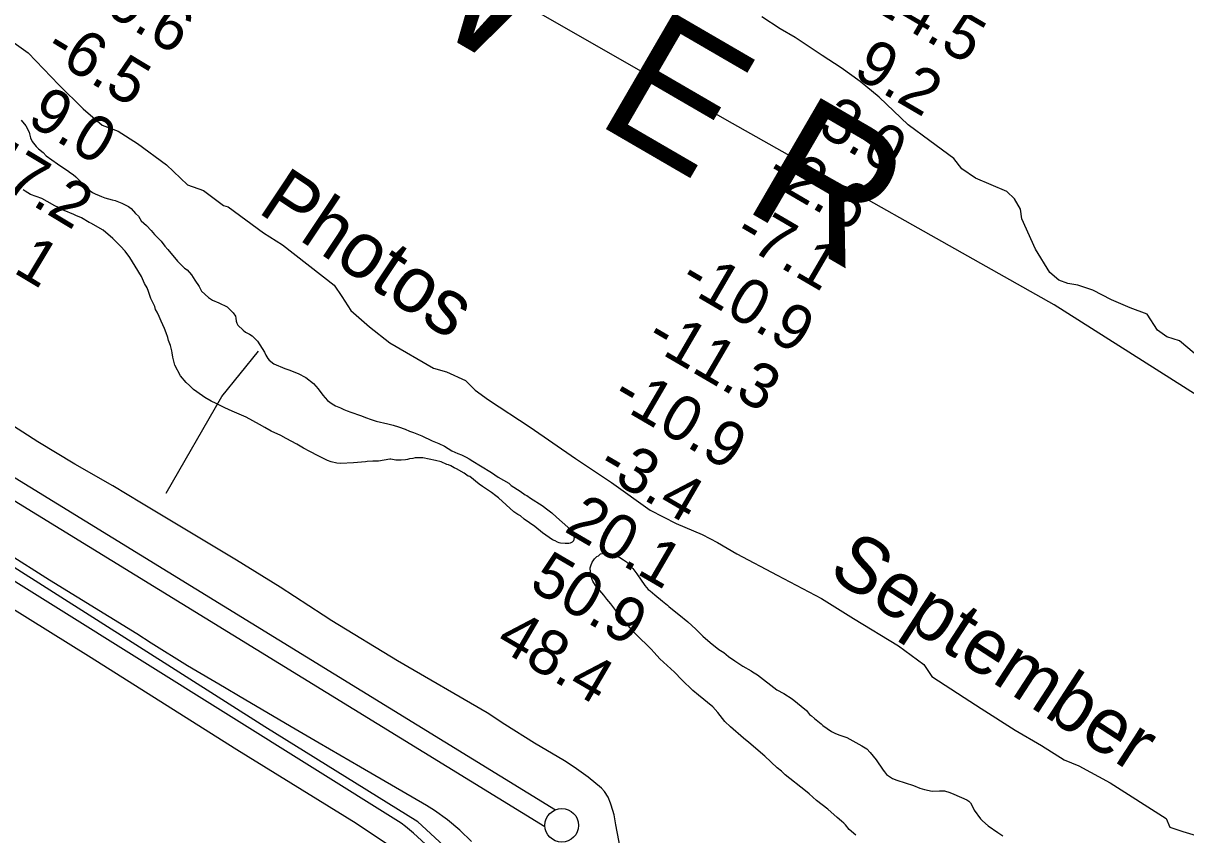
# Model space of a CAD drawing. Extents: x 3146026 to 3183936, y 897894 to 923344.
# Drawn here: x 3156715 to 3158441, y 912037 to 913242 of the extents above; entities that cross this region are included whole.
import ezdxf

# ---------------------------------------------------------------- set-up
doc = ezdxf.new("R2010")
doc.units = 0
for name, color, linetype in [('V-LEVE-TOET', 7, 'Continuous'), ('V-RIVR-EDGE', 7, 'Continuous'), ('V-RIVR-IDEN', 7, 'Continuous'), ('V-RIVR-RANG', 7, 'Continuous'), ('V-ROAD-CNTR', 7, 'Continuous'), ('V-SITE-VEGE', 7, 'Continuous'), ('V-SURV-LINE', 7, 'Continuous'), ('V-TOPO-BNDY', 7, 'Continuous'), ('V-TOPO-SHOR', 7, 'Continuous')]:
    doc.layers.add(name, color=color, linetype=linetype)

msp = doc.modelspace()

# ---------------------------------------------------------------- linework, layer by layer
at = {"layer": 'V-LEVE-TOET'}
for points in [[(3157594.4, 912051.6), (3157591.9, 912066.4), (3157587.8, 912081), (3157586.9, 912083.7), (3157583.1, 912092.6), (3157577.9, 912100.8), (3157573.2, 912106.2), (3157553.3, 912122.4), (3157532.5, 912137.4), (3157518.5, 912146.4), (3157473.7, 912172.7), (3157429.6, 912200.3), (3157403.4, 912217.7), (3157270.6, 912294.8), (3157173.1, 912354.6), (3157160.2, 912362.6), (3157096.1, 912404.3), (3157031.2, 912444.6), (3156890.3, 912529), (3156847.6, 912554.9), (3156791.6, 912586.8), (3156736.4, 912620.2), (3156684.8, 912653.1)], [(3157380.4, 912027), (3157363.1, 912043.5), (3157344.7, 912058.8), (3157325.3, 912072.9), (3157313.7, 912080.4), (3157215.3, 912137.4), (3157153.9, 912172.7), (3157118.5, 912193.8), (3157036.9, 912241.5), (3157013.4, 912255.5), (3156958.6, 912287.8), (3156904.5, 912321.4), (3156883.5, 912334.9), (3156753.6, 912414.9), (3156625.5, 912495.9)], [(3157603.4, 912005.1), (3157594.4, 912051.6)]]:
    msp.add_lwpolyline(points, dxfattribs=at)
at = {"layer": 'V-RIVR-EDGE'}
for points in [[(3158453.2, 912751.6), (3158431.6, 912770.3), (3158412.4, 912776.1), (3158399, 912786.2), (3158383.6, 912809.7), (3158358, 912818.9), (3158330.3, 912831.1), (3158302.9, 912845.5), (3158280.7, 912852.9), (3158265.5, 912855.3), (3158252.4, 912860.2), (3158239.1, 912871.8), (3158217.8, 912906), (3158197.2, 912951.4), (3158195.4, 912965.4), (3158186.6, 912981), (3158175.1, 912991.7), (3158128.8, 913011.6), (3158108.5, 913025.7), (3158096.6, 913040.6), (3158060.8, 913067.2), (3158028.5, 913090.7), (3157985.4, 913132), (3157957.1, 913154.9), (3157929.2, 913175.3), (3157900.9, 913193.7), (3157860.7, 913220.6), (3157838.8, 913233.4), (3157811.5, 913250.9)], [(3156669.9, 913235), (3156722.2, 913197.6), (3156767.7, 913150.3), (3156803.7, 913114.5), (3156831.8, 913090.3), (3156855.5, 913081.5), (3156884.4, 913063.2), (3156927.6, 913031.3), (3156958.9, 913001.9), (3156982.2, 912993.5), (3157012.3, 912970.8), (3157019.1, 912969.2), (3157071.3, 912930.6), (3157099.8, 912912.7), (3157176.6, 912852.7), (3157187.7, 912836), (3157201.1, 912815.3), (3157228.8, 912791.1), (3157259.3, 912767.2), (3157323.8, 912729.3), (3157343.3, 912724.1), (3157371.4, 912711.4), (3157385.6, 912697.1), (3157405.4, 912682.7), (3157467.6, 912642.1), (3157534.5, 912595.2), (3157588.3, 912559.7), (3157645.4, 912518.8), (3157684.2, 912498.8), (3157722.6, 912482.5), (3157745.6, 912470.9), (3157774.1, 912453.8), (3157834.3, 912422.3), (3157900, 912387.6), (3157947.2, 912357.8), (3158014.1, 912317.2), (3158051.7, 912289.7), (3158063.9, 912271.8), (3158111.5, 912240.8), (3158137.2, 912224.1), (3158187.5, 912192.2), (3158226.7, 912169.5), (3158260.3, 912148), (3158282.1, 912139.2), (3158328.5, 912114.1), (3158411.6, 912061.2), (3158417.2, 912048.1), (3158436.6, 912041.7), (3158456.4, 912035.7)]]:
    msp.add_lwpolyline(points, dxfattribs=at)
at = {"layer": 'V-ROAD-CNTR'}
msp.add_lwpolyline([(3157275.9, 912053.9), (3155853.5, 912943.3)], dxfattribs=at)
msp.add_arc((3157003.3, 911700), 446.8, 36.1726, 52.3968, dxfattribs=at)
at = {"layer": 'V-SITE-VEGE'}
for p, q in [((3156711.7, 913097.7), (3156718.9, 913089.3)), ((3156718.9, 913089.3), (3156723.6, 913079.7)), ((3156723.6, 913079.7), (3156724, 913077.2)), ((3156724, 913077.2), (3156725.7, 913071.3)), ((3156725.7, 913071.3), (3156728.3, 913065.9)), ((3156728.3, 913065.9), (3156733.8, 913058.8)), ((3156733.8, 913058.8), (3156737.6, 913055)), ((3156737.6, 913055), (3156744.3, 913049.6)), ((3156744.3, 913049.6), (3156748.9, 913044.6)), ((3156748.9, 913044.6), (3156765.8, 913032.9)), ((3156765.8, 913032.9), (3156773.4, 913027.5)), ((3156773.4, 913027.5), (3156780.5, 913023)), ((3156780.5, 913023), (3156785.2, 913019.6)), ((3156785.2, 913019.6), (3156789, 913017.1)), ((3156789, 913017.1), (3156792.8, 913013.8)), ((3156792.8, 913013.8), (3156804.1, 913002.1)), ((3156717.8, 912992.4), (3156714.8, 912994.1)), ((3156725.8, 912987.4), (3156717.8, 912992.4)), ((3156742.2, 912981.2), (3156725.8, 912987.4)), ((3156804.1, 913002.1), (3156812.2, 912994.2)), ((3156812.2, 912994.2), (3156814.3, 912992.9)), ((3156814.3, 912992.9), (3156817.6, 912990.4)), ((3156817.6, 912990.4), (3156821.4, 912988.4)), ((3156821.4, 912988.4), (3156827.3, 912985.9)), ((3156750.2, 912977), (3156742.2, 912981.2)), ((3156761.9, 912970.4), (3156750.2, 912977)), ((3156767, 912968.3), (3156761.9, 912970.4)), ((3156827.3, 912985.9), (3156831.1, 912984.6)), ((3156831.1, 912984.6), (3156836.1, 912982.6)), ((3156836.1, 912982.6), (3156846.7, 912979.3)), ((3156846.7, 912979.3), (3156851.3, 912978.5)), ((3156851.3, 912978.5), (3156861.4, 912974.7)), ((3156861.4, 912974.7), (3156871, 912969.7)), ((3156871, 912969.7), (3156874.8, 912966.8)), ((3156775.8, 912963.8), (3156767, 912968.3)), ((3156790.1, 912957.6), (3156775.8, 912963.8)), ((3156792.7, 912956.3), (3156790.1, 912957.6)), ((3156801.5, 912952.6), (3156792.7, 912956.3)), ((3156812.9, 912945.9), (3156801.5, 912952.6)), ((3156874.8, 912966.8), (3156881.6, 912959.3)), ((3156881.6, 912959.3), (3156885.8, 912955.1)), ((3156885.8, 912955.1), (3156890, 912948.5)), ((3156815.4, 912944.7), (3156812.9, 912945.9)), ((3156833.5, 912934.3), (3156815.4, 912944.7)), ((3156890, 912948.5), (3156897.6, 912941.4)), ((3156897.6, 912941.4), (3156904.8, 912933.9)), ((3156847.8, 912922.2), (3156833.5, 912934.3)), ((3156859.2, 912910.9), (3156847.8, 912922.2)), ((3156904.8, 912933.9), (3156909.5, 912928)), ((3156909.5, 912928), (3156919.6, 912918)), ((3156919.6, 912918), (3156925.1, 912910.5)), ((3156866, 912903), (3156859.2, 912910.9)), ((3156873.1, 912893.8), (3156866, 912903)), ((3156925.1, 912910.5), (3156929.7, 912905.5)), ((3156929.7, 912905.5), (3156943.7, 912888.3)), ((3156881.2, 912880.9), (3156873.1, 912893.8)), ((3156943.7, 912888.3), (3156954.2, 912877.9)), ((3156890.5, 912865.4), (3156881.2, 912880.9)), ((3156954.2, 912877.9), (3156958, 912875.4)), ((3156958, 912875.4), (3156964.8, 912868.3)), ((3156964.8, 912868.3), (3156969.4, 912860.4)), ((3156894.8, 912855.3), (3156890.5, 912865.4)), ((3156898.6, 912848.6), (3156894.8, 912855.3)), ((3156900.7, 912843.2), (3156898.6, 912848.6)), ((3156969.4, 912860.4), (3156975.8, 912850.8)), ((3156975.8, 912850.8), (3156979.6, 912844.1)), ((3156904.1, 912833.2), (3156900.7, 912843.2)), ((3156907.9, 912826), (3156904.1, 912833.2)), ((3156979.6, 912844.1), (3156989.7, 912834.5)), ((3156989.7, 912834.5), (3156996, 912830.7)), ((3156910, 912821), (3156907.9, 912826)), ((3156911.3, 912816.4), (3156910, 912821)), ((3156913.5, 912812.6), (3156911.3, 912816.4)), ((3156996, 912830.7), (3157005.3, 912826.6)), ((3157005.3, 912826.6), (3157017.5, 912820.4)), ((3157017.5, 912820.4), (3157019.1, 912819.1)), ((3157019.1, 912819.1), (3157026.7, 912811.6)), ((3156916.4, 912806.4), (3156913.5, 912812.6)), ((3156919.4, 912799.3), (3156916.4, 912806.4)), ((3156924.5, 912788.4), (3156919.4, 912799.3)), ((3157026.7, 912811.6), (3157029.7, 912806.6)), ((3157029.7, 912806.6), (3157030.6, 912803.6)), ((3157030.6, 912803.6), (3157031, 912799.5)), ((3157031, 912799.5), (3157031.9, 912796.5)), ((3157031.9, 912796.5), (3157033.6, 912793.2)), ((3156927, 912782.1), (3156924.5, 912788.4)), ((3156929.6, 912775), (3156927, 912782.1)), ((3157033.6, 912793.2), (3157041.2, 912786.1)), ((3157041.2, 912786.1), (3157044.9, 912783.2)), ((3157044.9, 912783.2), (3157050.8, 912779.8)), ((3157050.8, 912779.8), (3157054.6, 912777.3)), ((3156930.5, 912770.8), (3156929.6, 912775)), ((3156933.4, 912763.2), (3156930.5, 912770.8)), ((3156935.2, 912755.3), (3156933.4, 912763.2)), ((3157054.6, 912777.3), (3157062.6, 912769.4)), ((3157062.6, 912769.4), (3157073.2, 912753.1)), ((3156936, 912752.4), (3156935.2, 912755.3)), ((3156936.9, 912746.1), (3156936, 912752.4)), ((3156937.8, 912741.9), (3156936.9, 912746.1)), ((3157073.2, 912753.1), (3157074.9, 912748.9)), ((3157074.9, 912748.9), (3157077.9, 912743.9)), ((3156939.9, 912733.9), (3156937.8, 912741.9)), ((3156948.4, 912718.4), (3156939.9, 912733.9)), ((3157077.9, 912743.9), (3157080, 912741.4)), ((3157080, 912741.4), (3157086.7, 912736)), ((3157086.7, 912736), (3157103.1, 912728.9)), ((3157103.1, 912728.9), (3157109, 912727.3)), ((3156956.8, 912708.4), (3156948.4, 912718.4)), ((3157109, 912727.3), (3157122.9, 912721.5)), ((3157122.9, 912721.5), (3157134.3, 912715.7)), ((3157134.3, 912715.7), (3157145.6, 912706.9)), ((3156961.5, 912703.8), (3156956.8, 912708.4)), ((3156967.8, 912698), (3156961.5, 912703.8)), ((3156972.4, 912694.2), (3156967.8, 912698)), ((3156984.6, 912685.9), (3156972.4, 912694.2)), ((3157145.6, 912706.9), (3157152.8, 912699)), ((3157152.8, 912699), (3157159.6, 912689.4)), ((3156993.9, 912680.5), (3156984.6, 912685.9)), ((3157001.1, 912677.2), (3156993.9, 912680.5)), ((3157014.1, 912670.6), (3157001.1, 912677.2)), ((3157159.6, 912689.4), (3157166.3, 912681.5)), ((3157166.3, 912681.5), (3157173.5, 912676.5)), ((3157173.5, 912676.5), (3157178.6, 912673.6)), ((3157025, 912665.6), (3157014.1, 912670.6)), ((3157045.6, 912656.9), (3157025, 912665.6)), ((3157178.6, 912673.6), (3157185.7, 912670.7)), ((3157185.7, 912670.7), (3157190.8, 912668.2)), ((3157190.8, 912668.2), (3157195.8, 912666.1)), ((3157195.8, 912666.1), (3157201.3, 912664)), ((3157201.3, 912664), (3157215.6, 912659.5)), ((3157215.6, 912659.5), (3157224.4, 912655.8)), ((3157065.8, 912646.1), (3157045.6, 912656.9)), ((3157073.4, 912641.5), (3157065.8, 912646.1)), ((3157083.1, 912636.1), (3157073.4, 912641.5)), ((3157224.4, 912655.8), (3157229.9, 912653.7)), ((3157229.9, 912653.7), (3157238.7, 912650.8)), ((3157238.7, 912650.8), (3157255.9, 912646.7)), ((3157255.9, 912646.7), (3157263.9, 912645.1)), ((3157263.9, 912645.1), (3157271.9, 912642.6)), ((3157271.9, 912642.6), (3157282, 912638.9)), ((3157097, 912629.5), (3157083.1, 912636.1)), ((3157105, 912624.9), (3157097, 912629.5)), ((3157121, 912616.6), (3157105, 912624.9)), ((3157282, 912638.9), (3157288.3, 912636)), ((3157288.3, 912636), (3157294.2, 912633.9)), ((3157294.2, 912633.9), (3157306.4, 912629)), ((3157306.4, 912629), (3157321.9, 912621.9)), ((3157128.6, 912612.4), (3157121, 912616.6)), ((3157131.1, 912610.8), (3157128.6, 912612.4)), ((3157140.3, 912605.8), (3157131.1, 912610.8)), ((3157321.9, 912621.9), (3157331.6, 912617.8)), ((3157331.6, 912617.8), (3157340, 912613.6)), ((3157340, 912613.6), (3157351, 912607)), ((3157351, 912607), (3157360.2, 912602.8)), ((3157152.5, 912599.6), (3157140.3, 912605.8)), ((3157166.4, 912592.5), (3157152.5, 912599.6)), ((3157171.9, 912590.5), (3157166.4, 912592.5)), ((3157180.3, 912588.4), (3157171.9, 912590.5)), ((3157222.7, 912590.7), (3157205, 912589)), ((3157225.6, 912590.8), (3157222.7, 912590.7)), ((3157233.6, 912591.6), (3157225.6, 912590.8)), ((3157242, 912591.7), (3157233.6, 912591.6)), ((3157259.1, 912594.3), (3157242, 912591.7)), ((3157260.4, 912594.3), (3157259.1, 912594.3)), ((3157268, 912593.1), (3157260.4, 912594.3)), ((3157275.9, 912593.1), (3157268, 912593.1)), ((3157282.2, 912593.6), (3157275.9, 912593.1)), ((3157285.2, 912594), (3157282.2, 912593.6)), ((3157288.1, 912594.9), (3157285.2, 912594)), ((3157293.1, 912595.3), (3157288.1, 912594.9)), ((3157296.9, 912596.2), (3157293.1, 912595.3)), ((3157308.2, 912596.2), (3157296.9, 912596.2)), ((3157327.1, 912592.6), (3157308.2, 912596.2)), ((3157335.1, 912590.5), (3157327.1, 912592.6)), ((3157343.9, 912586.4), (3157335.1, 912590.5)), ((3157360.2, 912602.8), (3157365.3, 912600.8)), ((3157365.3, 912600.8), (3157372.4, 912597.4)), ((3157372.4, 912597.4), (3157377, 912595)), ((3157377, 912595), (3157382.1, 912591.6)), ((3157382.1, 912591.6), (3157393.9, 912584.6)), ((3157185.8, 912588), (3157180.3, 912588.4)), ((3157205, 912589), (3157185.8, 912588)), ((3157346, 912586), (3157343.9, 912586.4)), ((3157349.4, 912584.3), (3157346, 912586)), ((3157354.5, 912581.4), (3157349.4, 912584.3)), ((3157357.8, 912580.2), (3157354.5, 912581.4)), ((3157369.2, 912573.5), (3157357.8, 912580.2)), ((3157375.5, 912569.3), (3157369.2, 912573.5)), ((3157393.9, 912584.6), (3157409.9, 912574.6)), ((3157409.9, 912574.6), (3157420, 912567.5)), ((3157377.6, 912568.5), (3157375.5, 912569.3)), ((3157391.9, 912557.3), (3157377.6, 912568.5)), ((3157396.6, 912553.9), (3157391.9, 912557.3)), ((3157420, 912567.5), (3157435.6, 912558.8)), ((3157435.6, 912558.8), (3157439.4, 912555.4)), ((3157439.4, 912555.4), (3157452.4, 912547.1)), ((3157405.4, 912547.7), (3157396.6, 912553.9)), ((3157410, 912544.8), (3157405.4, 912547.7)), ((3157416.4, 912539.8), (3157410, 912544.8)), ((3157420.6, 912536.9), (3157416.4, 912539.8)), ((3157452.4, 912547.1), (3157460, 912541.7)), ((3157460, 912541.7), (3157462.5, 912540.5)), ((3157462.5, 912540.5), (3157468, 912536.7)), ((3157443.3, 912516.4), (3157420.6, 912536.9)), ((3157468, 912536.7), (3157485.3, 912525.5)), ((3157485.3, 912525.5), (3157493.7, 912519.2)), ((3157449.2, 912512.3), (3157443.3, 912516.4)), ((3157453, 912510.2), (3157449.2, 912512.3)), ((3157458.5, 912505.6), (3157453, 912510.2)), ((3157474.5, 912494.4), (3157458.5, 912505.6)), ((3157493.7, 912519.2), (3157499.6, 912514.7)), ((3157499.6, 912514.7), (3157506.7, 912508.4)), ((3157506.7, 912508.4), (3157523.2, 912493.4)), ((3157485.9, 912485.2), (3157474.5, 912494.4)), ((3157523.2, 912493.4), (3157526.1, 912490.5)), ((3157526.1, 912490.5), (3157531.7, 912480.4)), ((3157500.6, 912474.8), (3157485.9, 912485.2)), ((3157504.4, 912473.1), (3157500.6, 912474.8)), ((3157508.2, 912471.1), (3157504.4, 912473.1)), ((3157510.3, 912470.2), (3157508.2, 912471.1)), ((3157512.4, 912469.8), (3157510.3, 912470.2)), ((3157519.6, 912469), (3157512.4, 912469.8)), ((3157524.6, 912469.1), (3157519.6, 912469)), ((3157526.7, 912469.5), (3157524.6, 912469.1)), ((3157529.6, 912471.2), (3157526.7, 912469.5)), ((3157531.7, 912473.3), (3157529.6, 912471.2)), ((3157531.7, 912480.4), (3157532.5, 912477.9)), ((3157532.5, 912477.9), (3157531.7, 912473.3))]:
    msp.add_line(p, q, dxfattribs=at)
for points in [[(3157950.8, 912036.3), (3157941.2, 912044.5), (3157935.5, 912051.8), (3157932.9, 912054), (3157929.8, 912057), (3157923.3, 912062.2), (3157909.3, 912074.7), (3157892.7, 912087.7), (3157881.8, 912097.6), (3157876.1, 912101.9), (3157845.9, 912125.7), (3157840.3, 912131.3), (3157834.2, 912136.1), (3157815.8, 912153.3), (3157792.2, 912173.6), (3157784.3, 912180.1), (3157764.7, 912197), (3157756.4, 912205.2), (3157745.9, 912218.2), (3157738.4, 912226.8), (3157717.5, 912244.1), (3157708.7, 912251), (3157692.6, 912267), (3157681.6, 912278.2), (3157659.8, 912298.1), (3157651.5, 912307.2), (3157647.1, 912312.4), (3157640.5, 912318.9), (3157630.5, 912328), (3157620.9, 912337.9), (3157597.7, 912365.6), (3157587.2, 912379.5), (3157581, 912386.8), (3157576.7, 912392.4), (3157564.4, 912407.1), (3157560.4, 912413.2), (3157559.6, 912415.4), (3157557.8, 912421.9), (3157556.9, 912426.7), (3157556.4, 912433.2), (3157557.3, 912436.2), (3157559.4, 912441.5), (3157560.7, 912443.6), (3157562.9, 912446.3), (3157566.3, 912449.8), (3157568.9, 912451.1), (3157572, 912453.7), (3157577.6, 912455), (3157585.9, 912454.2), (3157595, 912452.1), (3157605.9, 912445.2), (3157610.3, 912442.2), (3157616, 912436.6), (3157619.9, 912432.2), (3157625.6, 912424.4), (3157637.4, 912407.1), (3157642.7, 912401.1), (3157645.7, 912398.9), (3157652.3, 912392.9)], [(3157652.3, 912392.9), (3157663.7, 912383.4), (3157671.1, 912377.7), (3157673.3, 912375.6), (3157678.5, 912371.3), (3157688.1, 912363.9), (3157701.6, 912352.7), (3157713.4, 912341.9), (3157723.9, 912331.5), (3157734.4, 912322.4), (3157747.5, 912312.1), (3157754.9, 912307.3), (3157761.9, 912301.7), (3157771.1, 912294.8), (3157782.9, 912287.1), (3157795.5, 912280.2), (3157797.3, 912278.9), (3157804.7, 912274.1), (3157833.5, 912252.1), (3157844, 912246.5), (3157856.6, 912238.8), (3157877.6, 912221.5), (3157882, 912215.4), (3157885, 912213.3), (3157889.4, 912209.4), (3157899.4, 912201.6), (3157902.1, 912199), (3157914.7, 912190), (3157919.9, 912187.8), (3157925.6, 912185.3), (3157937.4, 912181.4), (3157960, 912168.9), (3157967, 912164.2), (3157972.3, 912159), (3157981, 912148.2), (3157991.6, 912132.6), (3157993.7, 912130.4), (3157996.4, 912126.5), (3158000.7, 912123.1), (3158005.1, 912120.5), (3158011.6, 912117.9), (3158036.5, 912110.2), (3158046, 912105.9), (3158052.6, 912103.8), (3158064.3, 912101.7), (3158075.2, 912102.2), (3158078.7, 912102.2), (3158082.6, 912101.8), (3158090.4, 912099.7), (3158096.5, 912097.1), (3158115.7, 912088.5), (3158118.8, 912086.8), (3158120.9, 912084.2), (3158123.1, 912080.7), (3158126.7, 912073.3), (3158135.9, 912060.3), (3158138.9, 912057.3)], [(3158138.9, 912057.3), (3158147.2, 912050), (3158161.6, 912040.1), (3158169, 912035.3)]]:
    msp.add_lwpolyline(points, dxfattribs=at)
at = {"layer": 'V-SURV-LINE'}
for points in [[(3156108.2, 912931.8), (3157505.1, 912074)], [(3157489.4, 912048.5), (3156092.5, 912906.2)]]:
    msp.add_lwpolyline(points, dxfattribs=at)
msp.add_circle((3157514.3, 912050.8), 25, dxfattribs=at)
at = {"layer": 'V-TOPO-BNDY'}
msp.add_lwpolyline([(3162288, 912035.1), (3162225.5, 912006.3), (3162087.3, 911943.2), (3161778.1, 911799.8), (3161261.5, 911668.3), (3160960.6, 911648.5), (3160815.9, 911663.3), (3160685.6, 911676.6), (3160605.9, 911700), (3160140.6, 911840.9), (3159445.2, 912129.3), (3158861.9, 912432.7), (3158245.4, 912823.6), (3157767.9, 913092.7), (3157135.3, 913454.6), (3156545.8, 913785.7)], dxfattribs=at)
at = {"layer": 'V-TOPO-SHOR'}
for points in [[(3156926.8, 912543.9), (3157009.6, 912687.3), (3157064, 912754.6)], [(3158888.3, 910721.6), (3158612.2, 910882.1), (3158241.8, 911093.6), (3157894.4, 911295.8), (3157765.8, 911371.8), (3157664.5, 911439.7), (3157621.7, 911469.9), (3157578.1, 911521.9), (3157540.4, 911576.6), (3157518.5, 911629.4), (3157501, 911680.7), (3157482.3, 911742.1), (3157466.3, 911794.8), (3157453.4, 911856.1), (3157447.9, 911870.8), (3157414.7, 911932.6), (3157396.6, 911960.7), (3157364.2, 911997.8), (3157300.4, 912056.1), (3157073.3, 912197.1), (3156567.9, 912518.1)], [(3156694.8, 912375.4), (3156811.9, 912302.6), (3157031.8, 912163.3), (3157208.9, 912054.1), (3157271.7, 912011.8), (3157307.3, 911986.2), (3157337, 911957.9), (3157359.3, 911922.4), (3157374.5, 911891.6), (3157398, 911848.8), (3157426.4, 911768.3), (3157445.9, 911682.1), (3157456.3, 911635.4), (3157465.5, 911598.9), (3157486.3, 911562), (3157511.2, 911517.8), (3157543.6, 911480.7), (3157570.4, 911449.5), (3157607.2, 911413.7), (3157669.9, 911368.5), (3157701.3, 911347.3), (3157732.7, 911329.1)]]:
    msp.add_lwpolyline(points, dxfattribs=at)

# ---------------------------------------------------------------- texts
at = {"layer": 'V-RIVR-IDEN'}
for s, height, rotation, p in [('L   O W  E R', 200, 329.8355, (3156648.7, 913625.7)), ('Photos', 83, 326.3786, (3157061.1, 912961.8)), ('September', 83, 326.9896, (3157907.6, 912422.5))]:
    msp.add_text(s, height=height, rotation=rotation, dxfattribs=at).set_placement(p)
at = {"layer": 'V-RIVR-RANG'}
for s, rotation, p in [('-10.6', 328.9283, (3156765.1, 913299.4)), ('14.5', 329.6983, (3157966.2, 913267.6)), ('-6.5', 328.9283, (3156743.8, 913195.5)), ('9.2', 329.6983, (3157944.6, 913164.3)), ('9.0', 328.9283, (3156718.3, 913094)), ('3.0', 329.6983, (3157891.9, 913079.3)), ('47.2', 328.9283, (3156641, 913023.9)), ('-2.6', 329.6983, (3157813.9, 913009.1)), ('49.1', 328.9283, (3156591.6, 912936.9)), ('-7.1', 329.6983, (3157767.3, 912920.5)), ('-10.9', 329.6983, (3157686.1, 912852.2)), ('-11.3', 329.6983, (3157636.1, 912765.6)), ('-10.9', 329.6983, (3157585.6, 912679.2)), ('-3.4', 329.6983, (3157564.3, 912575.9)), ('20.1', 329.6983, (3157516.1, 912488.2)), ('50.9', 329.6983, (3157463.6, 912403.1)), ('48.4', 329.6983, (3157413.6, 912316.5))]:
    msp.add_text(s, height=67, rotation=rotation, dxfattribs=at).set_placement(p)

doc.saveas('drawing.dxf')
